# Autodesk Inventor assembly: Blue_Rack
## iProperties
Shininess: 64.0
Length Units: 11272
Angle Units: 11279
Time Units: 11290
Mass Units: 11286
Length Display Precision: 3
Angle Display Precision: 2
Compacted: True
Part Number: Blue_Rack
Document SubType Name: Assembly
Created: 2004-12
Designer: John Blackburn
Manufacturer: Standard
Standards Organization: Custom
Density: 0.0
Volumn: 0.0
Area: 0.0
PropertySet Name: Model Information
Control State: 0
Master: False
Checked Out: False
Author: John Blackburn
